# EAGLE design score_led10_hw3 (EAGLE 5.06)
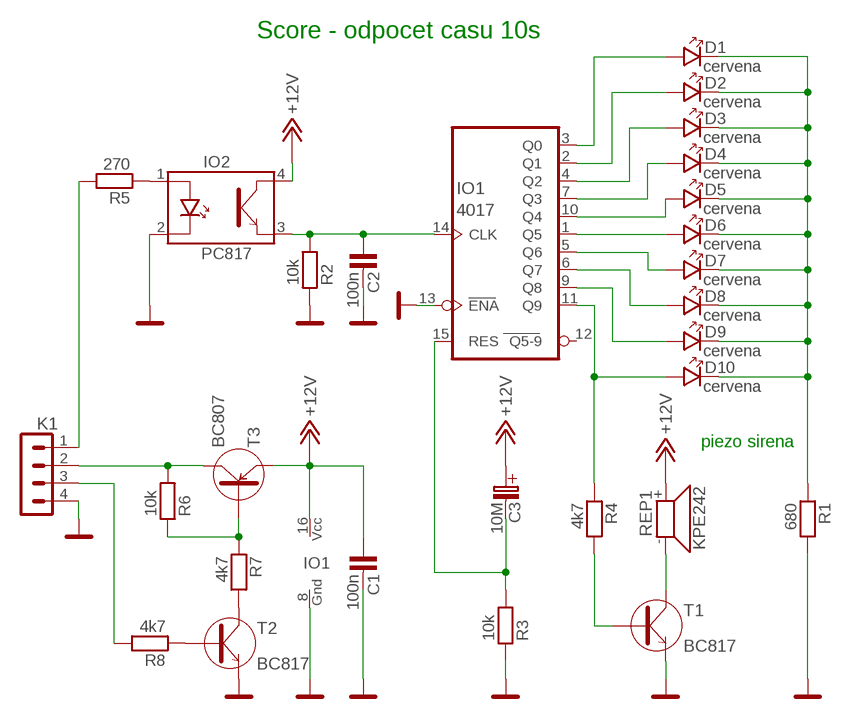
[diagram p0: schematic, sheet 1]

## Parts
C1  100n  C-KERAMIK_SMD_1206  [1206]
C2  100n  C-KERAMIK_SMD_1206  [1206]
C3  10M  1M/50V_SMD  [C_EL-SMD_B]
D1  cervena  LED_10  [LED_10]
D2  cervena  LED_10  [LED_10]
D3  cervena  LED_10  [LED_10]
D4  cervena  LED_10  [LED_10]
D5  cervena  LED_10  [LED_10]
D6  cervena  LED_10  [LED_10]
D7  cervena  LED_10  [LED_10]
D8  cervena  LED_10  [LED_10]
D9  cervena  LED_10  [LED_10]
D10  cervena  LED_10  [LED_10]
IO1  4017  [DIL16]
IO2  PC817  [DIL4]
K1  PSH02-04W  [PSH02-04W]
R1  680  R_SMD_1206  [1206]
R2  10k  R_SMD_1206  [1206]
R3  10k  R_SMD_1206  [1206]
R4  4k7  R_SMD_1206  [1206]
R5  270  R_SMD_1206  [1206]
R6  10k  R_SMD_1206  [1206]
R7  4k7  R_SMD_1206  [1206]
R8  4k7  R_SMD_1206  [1206]
REP1  KPE242  [KPE242]
T1  BC817  [SOT-23]
T2  BC817  [SOT-23]
T3  BC807  [SOT-23]

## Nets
+12V: C1.1 C3.+(C_EL+) IO1.16(VCC) IO2.4(C) REP1.+ T3.2(E)
CLK: K1.1 R5.2
GND: C1.2 C2.2 IO1.8(GND) IO1.13(ENA) IO2.2(K) K1.4 R1.2 R2.1 R3.1 T1.2(E) T2.2(E)
N$1: D5.A IO1.10(Q4)
N$2: D4.A IO1.7(Q3)
N$3: D3.A IO1.4(Q2)
N$4: D2.A IO1.2(Q1)
N$5: D1.A IO1.3(Q0)
N$6: D6.A IO1.1(Q5)
N$7: D7.A IO1.5(Q6)
N$8: D8.A IO1.6(Q7)
N$9: D9.A IO1.9(Q8)
N$10: D10.A IO1.11(Q9) R4.1
N$11: D1.K D2.K D3.K D4.K D5.K D6.K D7.K D8.K D9.K D10.K R1.1
N$12: IO2.1(A) R5.1
N$13: C2.1 IO1.14(CLK) IO2.3(E) R2.2
N$14: R4.2 T1.1(B)
N$15: REP1.- T1.3(C)
N$16: K1.2 R6.2 T3.3(C)
N$17: R6.1 R7.1 T3.1(B)
N$18: R7.2 T2.3(C)
N$19: R8.1 T2.1(B)
RESET: C3.-(C_EL-) IO1.15(RES) R3.2
ZAPNI: K1.3 R8.2
Unconnected: IO1.12(Q5-9)

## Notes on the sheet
- Score - odpocet casu 10s
- piezo sirena

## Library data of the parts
C1 C2 = #PaJa_23_e56:C-KERAMIK: Kondenzator - keramicky
C3 = #PaJa_C-el_2:1M/50V
D1-D10 = #PaJa_23_e56:LED: LED - jednobarevna
IO1 = #PaJa_23_e56:4017: IO - Johnsonuv citac
IO2 = #PaJa_23_e56:PC817: Optoclen
K1 = #PaJa_23_e56:PSH02-04: Konektory se zamkem - vidlice - 4pin
R1-R8 = #PaJa_23_e56:R: Rezistor
REP1 = #PaJa_23_e56:KPE242: Piezo-sirenka - 70dB - 3V az 16V
T1 T2 = #PaJa_23_e56:BC817: SMD tranzistor - NPN - ekv. BC337
T3 = #PaJa_23_e56:BC807: SMD tranzistor - PNP - ekv. BC327

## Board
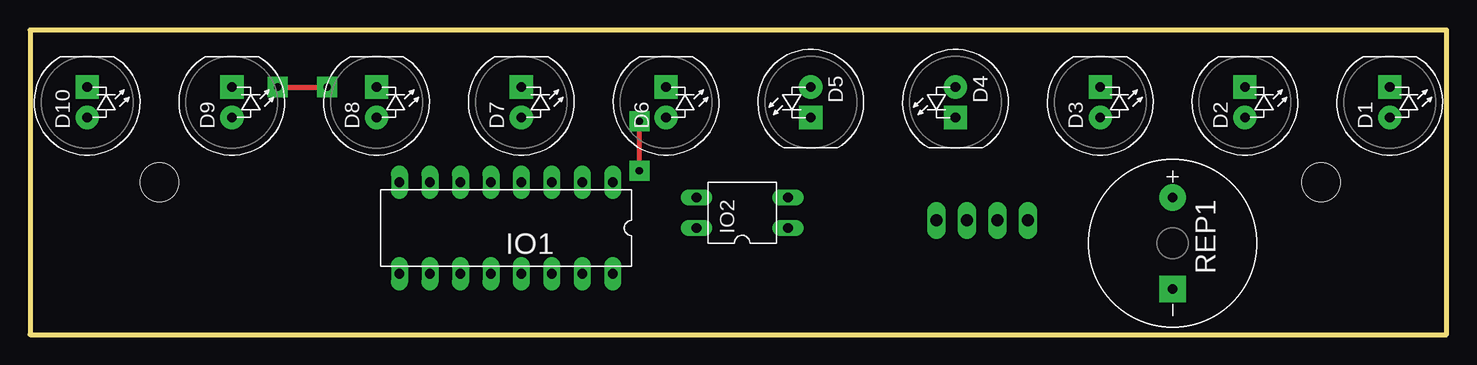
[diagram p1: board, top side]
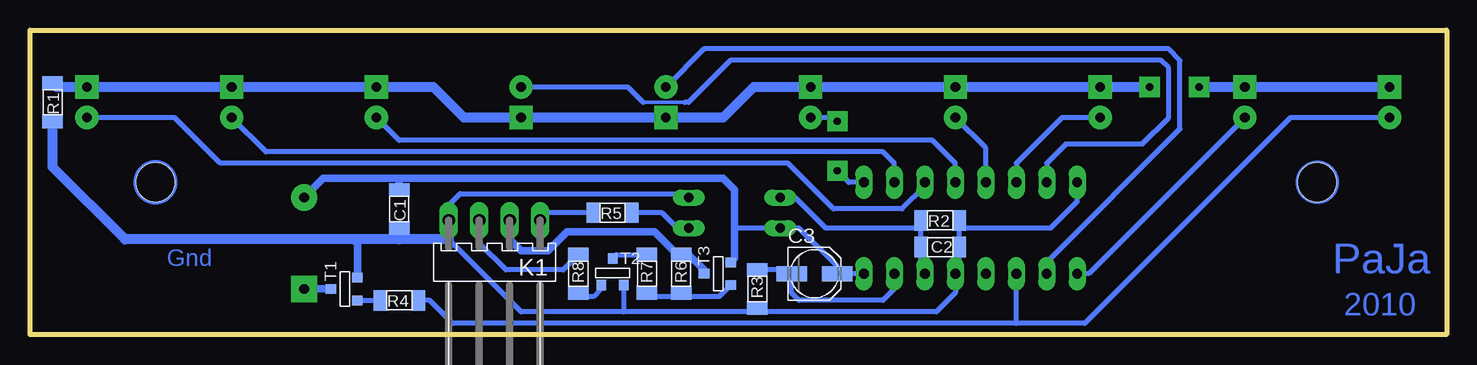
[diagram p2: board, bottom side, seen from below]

Size 118.1 x 25.39 mm. Coordinates in mm from the lower left corner, seen from the top.
Outline: 0,0 118.1,0 118.1,25.39 0,25.39 0,0
Copper layers (1*16): Top 0.035mm / dielectric 1.5mm / Bottom 0.035mm
Design rules "default": minimum track width 10mil, minimum drill 24mil, track to track 8mil, track to pad 8mil, pad to pad 8mil, via to via 8mil, smd to smd 8mil, copper to edge 40mil, drill to drill 8mil, minimum pad ring 10mil, minimum via ring 8mil, stop-mask expansion 4mil, vias tented up to drill 0mil, thermal gap 10mil
Holes 3.2 mm at 10.79,12.7 107.63,12.7

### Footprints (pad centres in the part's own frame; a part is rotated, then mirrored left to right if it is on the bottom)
1206 = smd 1.143 x 1.702: 1 -1.587,0; 2 1.587,0
C_EL-SMD_B = smd 2.54 x 1.27: + 1.905,0; - -1.905,0
LED_10 = drill 0.813 pad 1.93 round: A -1.27,0 | drill 0.813 pad 1.93 square: K 1.27,0
DIL16 = drill 0.813 pad 1.4 long: 1 -8.89,-3.81; 2 -6.35,-3.81; 3 -3.81,-3.81; 4 -1.27,-3.81; 5 1.27,-3.81; 6 3.81,-3.81; 7 6.35,-3.81; 8 8.89,-3.81; 9 8.89,3.81; 10 6.35,3.81; 11 3.81,3.81; 12 1.27,3.81; 13 -1.27,3.81; 14 -3.81,3.81; 15 -6.35,3.81; 16 -8.89,3.81
DIL4 = drill 0.813 pad 1.27 long: 1 -1.27,-3.81; 2 1.27,-3.81; 3 1.27,3.81; 4 -1.27,3.81
PSH02-04W = drill 1.016 pad 1.422 long: 1 -3.81,0; 2 -1.27,0; 3 1.27,0; 4 3.81,0
KPE242 = drill 0.813 pad 2.184 round: + -3.81,0 | drill 0.813 pad 2.184 square: - 3.81,0
SOT-23 = smd 0.787 x 0.889: 1 -0.953,-0.953; 2 0.953,-0.953; 3 0,1.27

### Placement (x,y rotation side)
C1  87.31,10.48 270 bottom
C2  42.23,7.3 0 bottom
C3  52.7,5.08 0 bottom
D1  113.35,19.37 90 top
D2  101.28,19.37 90 top
D3  89.22,19.37 90 top
D4  77.15,19.37 270 top
D5  65.09,19.37 270 top
D6  53.02,19.37 90 top
D7  40.96,19.37 90 top
D8  28.89,19.37 90 top
D9  16.83,19.37 90 top
D10  4.76,19.37 90 top
IO1  39.69,8.89 180 top
IO2  59.37,10.16 90 top
K1  79.38,9.52 180 bottom
R1  116.2,19.37 270 bottom
R2  42.23,9.52 180 bottom
R3  57.47,3.81 90 bottom
R4  87.31,2.86 180 bottom
R5  69.53,10.16 180 bottom
R6  63.82,5.08 90 bottom
R7  66.68,5.08 90 bottom
R8  72.39,5.08 90 bottom
REP1  95.25,7.62 270 top
T1  91.76,3.81 90 bottom
T2  69.53,5.08 0 bottom
T3  60.64,5.08 90 bottom

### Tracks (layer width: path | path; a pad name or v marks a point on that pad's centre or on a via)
+12V
  Bottom 0.406: IO1.16 C3.+ 50.8,5.72 53.97,8.89 IO2.4 59.37,8.89
  Bottom 0.61: 87.31,13.02 93.66,13.02 REP1.+ | 87.31,13.02 C1.1 | 87.31,13.02 60.32,13.02 59.37,12.07 59.37,8.89 59.37,6.35 T3.2
CLK
  Bottom 0.406: K1.1 74.93,10.16 R5.2
GND
  Bottom 0.406: 40.64,8.89 C2.2 40.64,5.4 IO1.13 40.96,3.49 42.54,1.9 57.15,1.9 | 40.64,8.89 R2.1 | 40.64,8.89 33.02,8.89 30.8,11.11 IO1.8 | 57.15,1.9 68.58,1.9 | 68.58,1.9 77.15,1.9 83.18,7.94 | 57.15,1.9 R3.1 | 68.58,1.9 T2.2 | 87.31,7.94 C1.2 | 91.12,7.94 90.81,7.62 | IO2.2 63.5,11.75 82.23,11.75 83.18,10.8 K1.4
  Bottom 0.61: 90.81,7.62 T1.2
  Bottom 0.813: K1.4 83.18,7.94 87.31,7.94 91.12,7.94 110.17,7.94 116.2,13.97 R1.2
N$1
  Bottom 0.406: D5.A 61.91,23.81 23.18,23.81 22.23,22.86 22.23,17.15 33.34,6.03 IO1.10
N$2
  Bottom 0.305: 63.5,19.37 66.99,19.37
  Bottom 0.406: IO1.7 33.34,14.29 31.75,15.88 25.4,15.88 23.18,18.1 23.18,22.23 23.81,22.86 59.69,22.86 63.18,19.37 63.5,19.37 | D4.A 68.26,20.64 66.99,19.37
N$3
  Bottom 0.406: D3.A 87.31,16.19 42.86,16.19 40.96,14.29 IO1.4
N$4
  Bottom 0.406: D2.A 98.43,15.24 46.99,15.24 46.04,14.29 IO1.2
N$5
  Bottom 0.406: IO1.3 43.5,12.38 45.4,10.48 51.12,10.48 54.93,14.29 102.23,14.29 106.04,18.1 D1.A
N$6  (via drill 0.6 pad 1.68)
  Top 0.406: v50.8,13.65 v50.8,17.78
  Bottom 0.406: D6.A 51.12,18.1 v50.8,17.78 | v50.8,13.65 49.85,12.7 IO1.1
N$7
  Bottom 0.406: D7.A 38.42,15.56 IO1.5
N$8
  Bottom 0.406: D8.A 32.07,18.1 35.88,14.29 IO1.6
N$9
  Bottom 0.406: D9.A 29.85,5.08 IO1.9
N$10
  Bottom 0.406: 35.88,0.95 IO1.11 | D10.A 13.02,18.1 30.16,0.95 35.88,0.95 | 35.88,0.95 82.87,0.95 84.77,2.86 R4.1
N$11  (via drill 0.6 pad 1.68)
  Top 0.406: v20.64,20.64 v24.76,20.64
  Bottom 0.406: 115.89,20.64 R1.1
  Bottom 0.813: D10.K D9.K v20.64,20.64 | v24.76,20.64 D8.K D7.K D6.K 57.78,20.64 60.32,18.1 D5.K D4.K 81.92,18.1 84.45,20.64 D3.K D2.K D1.K 115.89,20.64
N$12
  Bottom 0.406: IO2.1 64.14,8.89 65.4,10.16 R5.1
N$13
  Bottom 0.406: IO1.14 43.5,5.72 43.82,5.72 C2.1 R2.2 43.82,8.89 51.75,8.89 54.29,11.43 IO2.3
N$14
  Bottom 0.406: T1.1 R4.2
N$15
  Bottom 0.61: T1.3 REP1.-
N$16
  Bottom 0.406: 63.18,6.67 R6.2
  Bottom 0.61: K1.2 78.1,7.94 77.15,6.98 74.93,6.98 73.34,8.57 66.04,8.57 64.14,6.67 R6.2 | T3.3 61.91,5.4 63.18,6.67
N$17
  Bottom 0.406: T3.1 60.64,3.18 63.82,3.18 | 63.82,3.18 66.04,3.18 R7.1 | 63.82,3.18 R6.1
N$18
  Bottom 0.406: R7.2 69.21,6.67 T2.3
N$19
  Bottom 0.406: T2.1 70.48,3.81 71.12,3.18 72.07,3.18 R8.1
RESET
  Bottom 0.406: IO1.15 46.04,3.81 46.99,2.86 53.97,2.86 54.61,3.49 C3.- 54.93,5.4 R3.2
ZAPNI
  Bottom 0.406: K1.3 80.65,7.62 78.42,5.4 73.66,5.4 R8.2
(copper drawn outside any net)
  shapes: Bottom circle x4

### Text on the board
Bottom: Gnd | PaJa | 2010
